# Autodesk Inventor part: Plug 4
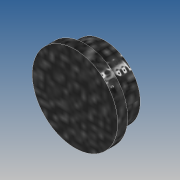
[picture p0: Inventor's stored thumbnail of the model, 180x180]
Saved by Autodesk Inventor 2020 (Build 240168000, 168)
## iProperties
Created: 2019-10
Part Number: Plug 4
Material: Generic
Document SubType Name: Modeling
Designer: yello
Density: 1 g/cm^3
Appearance: Default
Author: yello
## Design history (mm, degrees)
sketch "Sketch1"
  geometry: C1 r 4.25 at (0, 0); 1 further point
  constraints: 1 centre point, 1 coincident
  dimensions: "d0" = 8.5 diameter of C1
extrude "Extrusion1" new body sketch "Sketch1" distance "d1" = 1; taper "d2" = 0 deg
sketch "Sketch2"
  geometry: C1 r 3.5 at (0, 0); 1 further point
  constraints: 1 centre point, 1 coincident
  dimensions: "d3" = 7 diameter of C1
extrude "Extrusion2" join sketch "Sketch2" distance "d4" = 2; taper "d5" = 0 deg
body "Solid1"
